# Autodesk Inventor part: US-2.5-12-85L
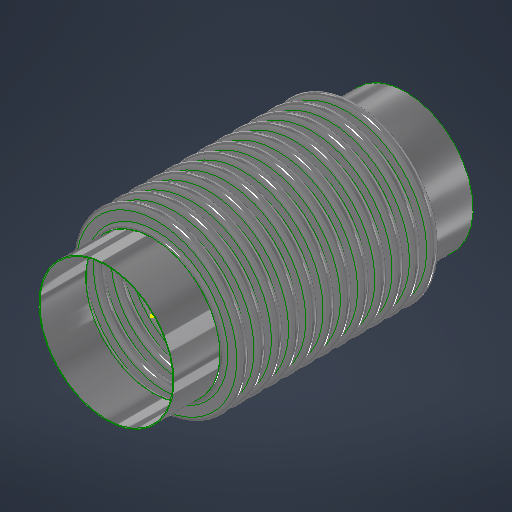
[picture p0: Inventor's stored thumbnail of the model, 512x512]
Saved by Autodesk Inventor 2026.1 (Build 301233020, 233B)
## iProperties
Category: 26 GA (0.018 THICK)
RuleStatus: InUse
Created: 2026-07
Part Number: US-2.5-12-85L
Project: =STOCK BELLOWS: <Stock Number><SFILL>
Material: ASTM A240-304
Description: =STOCK BELLOWS: <Stock Number>, <SID_> I.D., <SOD_> O.D., <SPLY_> PLY, <Category>, <SNET_CONS> CONS.<PITCH_><STANGENT_> TANGENT<SFILL>
Document SubType Name: Sheet Metal
Designer: LC
Stock Number: U.S-2.5-12-85L
Surface Area: 659.127 cm^2
Volume: 56.61 cm^3
Sheet Metal Rule: Default
Appearance: STAINLESS STEEL
NET_TUBE: 3.428
COUNTER: 1.500
PBAR: 1.214
PSET: 5.356
PLY: 2
CONS: 2
THK: 0.036
ID: 4.500
OD: 5.500
CONS_: 2
TANGENT: 0.500
PITCH: 0.375
BELLOWS_UPSET: 0.000
NET_CONS: 2
S_CONS: 0
Description_Units: 0
ID_M: 114.30 mm
OD_M: 139.70 mm
THK_M: 0.91 mm
ID_U: 4.500 in
OD_U: 5.500 in
THK_U: 0.036 in
TANGENT2: 0.500
d79: 1.000
d82: 1.000
d83: 26.000
d84: 24.000
d80: 2.571
d81: 10
SID: 2.375
SCONS_: 12
SPITCH: 0.250
SBELLOWS_UPSET: 0.000
SNET_CONS: 12
SS_CONS: 0
SCONS: 8
d174: 8
d177: 0.018
d178: 2.375
d179: 3.000
d180: 0.375
d181: 1.000
d182: 0.000
d190: 8
d191: 1
d192: 1
d193: 8
d194: 0
PART_NUMBER: U.S-2.5-12-85L
PRESSURE: 85
SIZE: 2.50
STANGENT_: 1.000
d214: 8
d217: 0.030
d218: 6.625
d219: 8.125
d220: 0.500
d221: 1.000
d222: 0.000
d230: 8
d231: 1
d232: 1
d233: 8
d234: 0
STANGENT: 4.000
SPLY_: 1
STHK_: 0.018
SID_: 2.900
SOD_: 3.700
SPITCH_: 0.375
STANGENT__: 1.000
SBELLOWS_UPSET_: 0.000
SDIFF_TAN: 1.000
TAN_TO_TAN: 0.750 in
d252: 2
d275: 2
d287: 0.050
d289: 0.500
d290: 0.000
d263: 2
d265: 1
d268: 2
d269: 0
d286: 2
d288: 1
d291: 2
d292: 0
SOD_NECK: 2 15/16
CFILL: .
SFILL: .
PITCH_: =, <SPITCH_> PITCH,
SREROLL: 0.750
MATTABLE: 20 GA (0.036 THICK)
MESH: ,
CSECT: 2
Author: LC
Keywords: 20 GA (0.036 THICK)
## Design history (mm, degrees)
sketch "Sketch2"
  geometry: L1 (0, -183.595)-(0, 600.956) reference; L2 (58.979, 0)-(57.15, 0); L3 (60.446, -1.467)-(66.554, -1.467); L4 (60.446, -3.296)-(66.554, -3.296); L5 (66.554, -8.058)-(60.446, -8.058); L6 (66.554, -6.229)-(60.446, -6.229); L7 (58.979, -9.525)-(57.15, -9.525); L8 (60.446, 0)-(60.446, -9.525); L9 (66.554, -4.762)-(69.85, -4.763); L10 (57.15, 0)-(57.15, -9.525); L11 (20.376, 102.841)-(20.376, 101.926); L12 (58.262, 488.877)-(58.262, 349.177); L13 (58.262, 479.352)-(58.262, 339.652); L14 (93.133, -58.817)-(93.133, -71.517); L15 (118.746, -66.401)-(118.746, -66.401); L16 (66.554, -6.229)-(66.554, -8.058); L17 (60.446, -6.229)-(60.446, -8.058); L18 (60.446, -7.144)-(66.554, -7.144); L19 (69.85, 0)-(69.85, -9.525); L20 (-66.554, -6.229)-(-66.554, -8.058); L21 (-66.554, -1.467)-(-60.446, -1.467); L22 (-66.554, -3.296)-(-60.446, -3.296); L23 (-60.446, -6.229)-(-66.554, -6.229); L24 (-66.554, -7.144)-(-60.446, -7.144); L25 (-60.446, -8.058)-(-66.554, -8.058); L26 (-60.446, -6.229)-(-60.446, -8.058); L27 (-57.15, -2.522)-(-57.15, -12.047); L28 (-60.446, -4.763)-(-57.15, -4.763); L29 (-66.554, 3.828)-(-66.554, -9.525); L30 (-68.021, 0)-(-69.85, 0); L31 (-69.85, 0)-(-69.85, -9.525); L32 (-68.021, -9.525)-(-69.85, -9.525); A1 r 1.467 centre (60.446, 0) between (58.979, 0) and (60.446, -1.467); A2 r 3.296 centre (60.446, 0) between (57.15, 0) and (60.446, -3.296); A3 r 3.296 centre (66.554, -4.762) between (66.554, -8.058) and (66.554, -1.467); A4 r 1.467 centre (66.554, -4.762) between (66.554, -6.229) and (66.554, -3.296); A5 r 1.467 centre (60.446, -9.525) between (60.446, -8.058) and (58.979, -9.525); A6 r 3.296 centre (60.446, -9.525) between (60.446, -6.229) and (57.15, -9.525); A7 r 2.381 centre (66.554, -4.762) between (66.554, -7.144) and (68.936, -4.762); A8 r 2.381 centre (60.446, -9.525) between (60.446, -7.144) and (58.064, -9.525); A9 r 1.467 centre (-66.554, -9.525) between (-66.554, -8.058) and (-68.021, -9.525); A10 r 1.467 centre (-60.446, -4.763) between (-60.446, -6.229) and (-60.446, -3.296); A11 r 2.381 centre (-60.446, -4.763) between (-60.446, -7.144) and (-58.064, -4.763); A12 r 3.296 centre (-60.446, -4.763) between (-60.446, -8.058) and (-60.446, -1.467); A13 r 2.381 centre (-66.554, -9.525) between (-66.554, -7.144) and (-68.936, -9.525); A14 r 3.296 centre (-66.554, -9.525) between (-66.554, -6.229) and (-69.85, -9.525); A15 r 1.467 centre (-66.554, 0) between (-68.021, 0) and (-66.554, -1.467); A16 r 3.296 centre (-66.554, 0) between (-69.85, 0) and (-66.554, -3.296); 10 further points
  constraints: 62 end point, 38 point on circle, 20 tangent, 16 centre point, 12 parallel, 9 midpoint, 7 vertical, 6 coincident, 6 concentric, 6 point on line, 4 equal radius, 4 perpendicular, 3 horizontal, 1 collinear, 1 horizontal alignment, 10 other
  dimensions: "THK" = 0.9144 distance of L11.start L11.end; "ID" = 114.3 distance of L11.end point (20.376, -12.374); "OD" = 139.7 distance of L12.start L12.end; "PITCH" = 9.525 distance of L12.start L13.start; "TANGENT" = 12.7 distance of L14.start L14.end; "BELLOWS_UPSET" = 0 distance of L15.start L15.end; "d43" = 114.3 diameter of L10 L1 (= ID); "d44" = 139.7 diameter of L9.end L1 (= OD); "d45" = 1.8288 distance between parallel lines of L5 L6 (computed from THK, PLY); "d46" = 3.29565 radius of A3 (computed from PITCH, THK, PLY); "UPSET_PITCH" = 9.525 distance of L2.end L7.end (derived); "SIDEWALL_ANGLE" = 0 deg angle of L3 L9 (derived); "CON_GAP" = 2.9337 distance of point (60.446, -6.229) point (60.446, -3.296) (derived); "TAN1" = 3.74046 dimension on A8 (derived); "TAN2" = 3.74046 dimension on A7 (derived); "LEG1" = 6.1087 distance of L18.start L18.end (derived); "d278" = 1.8288 distance between parallel lines of L25 L23 (derived); "d279" = 3.29565 radius of A12 (derived); "d280" = 9.525 distance of L30.end L31.end (derived); "d281" = 360 deg dimension on L21 L28 (derived); "d282" = 2.9337 distance of point (-66.554, -6.229) point (-66.554, -3.296) (derived); "d283" = 3.74046 dimension on A13 (derived); "d284" = 3.74046 dimension on A11 (derived); "d285" = 6.1087 distance of L24.start L24.end (derived); "d293" = 114.3 diameter of L27 L1 (derived); "d294" = 139.7 diameter of L31 L1 (derived)
  node "Sketch Rectangular Pattern1" dims "d31" = 25.4, "ID" = 114.3
  node "Sketch Rectangular Pattern2" dims "d39" = 25.4, "PITCH" = 9.525
revolve "CONS" stored, may be unused: angle "d48" = 90 deg
node "BELLOW MIDPLANE"
pattern_linear "Rectangular Pattern2" dims "d52" = 9.525 (= UPSET_PITCH)
sketch "Sketch5"
  geometry: C1 r 58.979 at (0, 0) reference; C2 r 57.15 at (0, 0) reference
extrude "TANGENT" new body sketch "Sketch5" distance "d53" = 12.7 (= TANGENT); taper "d54" = 0 deg
revolve "SAMETAN" stored, may be unused: angle "d65" = 90 deg
revolve "DIFFTAN" stored, may be unused: angle "d70" = 90 deg
sketch "Sketch9"
  geometry: L1 (58.391, 0)-(-58.391, 0) reference; L2 (0, -17.78)-(0, 17.78) reference; L3 (41.708, 0)-(-41.708, 0); L4 (41.708, -11.906)-(41.708, 11.906); L5 (29.008, -11.906)-(29.008, 11.906); L6 (15.418, 11.906)-(15.418, -11.906); L7 (-29.008, -11.906)-(-29.008, 11.906); L8 (-41.708, -11.906)-(-41.708, 11.906); L9 (40.914, -11.906)-(40.914, 11.906); L10 (41.708, -11.906)-(40.914, -11.906); L11 (41.708, 11.906)-(40.914, 11.906); L12 (15.815, 11.906)-(15.022, 11.906); L13 (15.022, 11.906)-(15.022, -11.906); L14 (15.022, -11.906)-(15.815, -11.906); L15 (15.815, -11.906)-(15.815, 11.906); L16 (-15.815, 11.906)-(-15.815, -11.906); L17 (-15.418, 11.906)-(-15.418, -11.906); L18 (-15.815, -11.906)-(-15.022, -11.906); L19 (-15.022, -11.906)-(-15.022, 11.906); L20 (-15.022, 11.906)-(-15.815, 11.906); L21 (-41.708, -11.906)-(-40.914, -11.906); L22 (-40.914, -11.906)-(-40.914, 11.906); L23 (-40.914, 11.906)-(-41.708, 11.906); L24 (-41.708, 11.906)-(-41.708, -11.906); L25 (41.708, -0.397)-(-41.708, -0.397); L26 (-41.708, -0.397)-(-41.708, 0.397); L27 (-41.708, 0.397)-(41.708, 0.397); L28 (41.708, 0.397)-(41.708, -0.397); L29 (-41.708, 11.906)-(41.708, 11.906); L30 (41.708, 11.906)-(41.708, 12.7); L31 (41.708, 12.7)-(-41.708, 12.7); L32 (-41.708, 12.7)-(-41.708, 11.906); L33 (41.708, -11.906)-(-41.708, -11.906); L34 (-41.708, -11.906)-(-41.708, -12.7); L35 (-41.708, -12.7)-(41.708, -12.7); L36 (41.708, -12.7)-(41.708, -11.906); 30 further points
  constraints: 68 end point, 13 midpoint, 13 parallel, 8 horizontal, 7 perpendicular, 6 equal length, 3 point on line, 2 vertical, 14 other
  dimensions: "d115" = 23.8125 distance of L4.start L4.end (derived); "d116" = 12.7 distance between parallel lines of L4 L5 (derived); "d117" = 13.58962 distance between parallel lines of L5 L6 (derived); "d125" = 44.42645 distance between parallel lines of L7 L6 (derived); "d127" = 12.7 distance between parallel lines of L8 L7 (derived); "d128" = 26.28962 distance between parallel lines of L6 L4 (derived); "d130" = 83.41607 distance between parallel lines of L8 L4 (derived); "RULER_THK" = 0.79375 distance between parallel lines of L4 L9; "d135" = 0.79375 distance of L13.end L14.end (derived); "d138" = 30.83684 distance of L13.end L16.end (derived); "d143" = 0.79375 distance of L22.end L8.end (derived); "d144" = 0.79375 distance between parallel lines of L27 L25 (derived)
extrude "RULER" join sketch "Sketch9" distance "d149" = 0.79375 (derived); taper "d150" = 0 deg
extrude "BARS" join sketch "Sketch9" distance "d151" = 0.79375 (derived); taper "d152" = 0 deg
pattern_linear "Rectangular Pattern4" dims "d155" = 30.83684 (derived)
sketch "Sketch13"
  geometry: L1 (93.149, -52.467)-(93.149, -77.867); L2 (37.287, 0)-(36.83, 0); L3 (37.287, -9.525)-(36.83, -9.525); L4 (44.38, -7.372)-(39.44, -7.372); L5 (44.38, -6.915)-(39.44, -6.915); L6 (44.38, -4.762)-(46.99, -4.762); L7 (39.44, -2.153)-(44.38, -2.153); L8 (39.44, 0)-(39.44, -9.525); L9 (36.83, 0)-(36.83, -9.525); L10 (58.254, -367.738)-(58.254, -461.718); L11 (58.254, -377.263)-(58.254, -471.243); L12 (58.254, -396.313)-(58.254, -490.293); L13 (58.254, -405.838)-(58.254, -499.818); L14 (58.254, -415.363)-(58.254, -509.343); L15 (58.254, -424.888)-(58.254, -518.868); L16 (58.254, -434.413)-(58.254, -528.393); L17 (58.254, -386.788)-(58.254, -480.768); L18 (20.376, 102.383)-(20.376, 101.926); L19 (39.44, -2.61)-(44.38, -2.61); L20 (0, -640.324)-(0, 226.168) reference; L21 (-23.752, 0)-(142.514, 0) reference; A1 r 2.153 centre (39.44, 0) between (37.287, 0) and (39.44, -2.153); A2 r 2.153 centre (39.44, -9.525) between (39.44, -7.372) and (37.287, -9.525); A3 r 2.61 centre (39.44, -9.525) between (39.44, -6.915) and (36.83, -9.525); A4 r 2.153 centre (44.38, -4.762) between (44.38, -6.915) and (44.38, -2.61); A5 r 2.61 centre (44.38, -4.762) between (44.38, -7.372) and (44.38, -2.153); A6 r 2.61 centre (39.44, 0) between (36.83, 0) and (39.44, -2.61); 6 further points; 1 other entity
  constraints: 38 end point, 15 point on circle, 9 tangent, 6 centre point, 6 parallel, 5 vertical alignment, 4 point on line, 4 vertical, 3 coincident, 3 concentric, 2 collinear, 2 equal radius, 1 horizontal, 1 perpendicular, 23 other
  dimensions: "SBELLOWS_UPSET_" = 0 distance of point (118.762, -66.401) point (118.762, -66.401); "STOTAL_THK_BELLOW__" = 0.4572 distance between parallel lines of L4 L5 (derived); "d224" = 2.60985 radius of A5 (derived); "d225" = 9.525 distance of L2.end L3.end (derived); "SSIDEWALL_ANGLE_" = 0 deg angle of L7 L6 (derived); "SSCON_GAP_" = 4.3053 distance of point (39.44, -6.915) point (39.44, -2.61) (derived); "d235" = 73.66 diameter of L9 L20 (derived); "d236" = 93.98 diameter of L6.end L20 (derived)
  node "Sketch Rectangular Pattern4" dims "d228" = 25.4
  node "Sketch Rectangular Pattern5" dims "d229" = 25.4
revolve "SBELLOW" stored, may be unused: angle "d197" = 90 deg
pattern_linear "Rectangular Pattern5" dims "d204" = 9.525 (derived)
revolve "STANGENT" stored, may be unused: angle "d240" = 90 deg
revolve "SSAMETAN" stored, may be unused: angle "d241" = 90 deg
revolve "SDIFFTAN" stored, may be unused: angle "d246" = 90 deg
revolve "INVCON" stored, may be unused: angle "d295" = 90 deg
pattern_linear "Rectangular Pattern6" dims "d298" = 9.525 (derived)
revolve "INVTANGENT" stored, may be unused: angle "d302" = 90 deg
revolve "INVSAMETAN" stored, may be unused: angle "d307" = 90 deg
revolve "INVDIFFTAN" stored, may be unused: angle "d312" = 90 deg
sketch "ID BELLOW MOUNT CALC"
  geometry: L1 (44.45, 0)-(38.1, 0); L2 (38.1, 0)-(38.1, 12.7); L3 (38.1, 12.7)-(44.45, 12.7); L4 (44.45, 12.7)-(44.45, 0); L5 (36.513, 12.7)-(34.684, 12.7); L6 (34.684, 12.7)-(34.684, 0); L7 (34.684, 0)-(36.513, 0); L8 (36.513, 0)-(36.513, 12.7); L9 (0, -2.54)-(0, 15.24) reference; L10 (-8.89, 0)-(53.34, 0) reference; 1 further point
  constraints: 16 end point, 5 parallel, 2 collinear, 2 horizontal, 2 perpendicular
  dimensions: "d314" = 12.7 distance of L5.end L6.end (derived); "d315" = 1.8288 distance of L5.start L5.end (derived); "IG" = 1.5875 distance between parallel lines of L2 L8; "PIPE_OD" = 88.9 diameter of L4 L9; "PIPE_WALL" = 6.35 distance of L2.end L3.end; "ID_MT_BELLOW" = 69.3674 diameter of L6 L9 (derived)
revolve "CFILL" stored, may be unused: angle "d320" = 90 deg
pattern_linear "Rectangular Pattern7" dims "d323" = 9.525 (derived)
revolve "SFILL" stored, may be unused: angle "d324" = 90 deg
pattern_linear "Rectangular Pattern8" dims "d327" = 9.525 (derived)
node "STOCK BELLOW MIDPLANE"
sketch "Sketch21"
  geometry: L1 (0, -100.013)-(0, 100.013) reference; L2 (-100.013, 0)-(100.013, 0) reference; L3 (-0.099, 71.437)-(0.099, 71.437); L4 (0.099, 71.437)-(0.099, 55.562); L5 (0.099, 55.562)-(-0.099, 55.562); L6 (-0.099, 55.562)-(-0.099, 71.437); C1 r 55.562 at (0, 0); C2 r 71.437 at (0, 0); 3 further points
  constraints: 8 end point, 2 centre point, 2 coincident, 2 parallel, 2 tangent, 1 horizontal, 1 perpendicular, 1 other
  dimensions: "d329" = 111.125 diameter of C1 (derived); "d330" = 142.875 diameter of C2 (derived); "d331" = 0.19844 distance of L3.start L3.end
extrude "CLAMSHELL" cut sketch "Sketch21" extent not by distance; stored distance "d332" = 0; taper "d333" = 0 deg
pattern_circular "Circular Pattern1" dims angle "d335" = 180 deg (derived)
node "BELLOW"
sketch "Sketch6"
  geometry: L1 (-19.05, 58.979)-(-6.35, 58.979); L2 (-6.35, 58.979)-(-6.35, 57.15); L3 (-6.35, 57.15)-(-19.05, 57.15); L4 (-19.05, 57.15)-(-19.05, 58.979); L5 (2.54, 0)-(-59.69, 0) reference; L6 (-38.1, -108.388)-(-38.1, 156.601) reference; 1 further point
  constraints: 8 end point, 2 parallel, 1 horizontal, 1 perpendicular
  dimensions: "d61" = 12.7 distance of L2.end L3.end (derived); "d62" = 1.8288 distance of L1.end L2.end (derived); "d63" = 114.3 diameter of L3 L5 (derived); "d64" = 19.05 distance between parallel lines of L4 L6 (derived)
sketch "Sketch12"
  geometry: 1 further point
sketch "Sketch14"
  geometry: L1 (-25.4, 37.287)-(0, 37.287); L2 (0, 37.287)-(0, 36.83); L3 (0, 36.83)-(-25.4, 36.83); L4 (-25.4, 36.83)-(-25.4, 37.287); L5 (5.08, 0)-(-30.48, 0) reference; L6 (0, -8.89)-(0, 53.34) reference; 1 further point
  constraints: 8 end point, 2 parallel, 1 collinear, 1 horizontal, 1 perpendicular
  dimensions: "d237" = 0.4572 distance of L3.end L1.start (derived); "d238" = 73.66 diameter of L3 L5 (derived); "d239" = 25.4 distance of L1.start L1.end (derived); "SOD_NECK" = 74.5744 diameter of L1 L5 (derived)
sketch "Sketch15"
  geometry: L1 (-8.89, 0)-(53.34, 0) reference; L2 (36.83, -114.3)-(37.287, -114.3); L3 (37.287, -114.3)-(37.287, -139.7); L4 (37.287, -139.7)-(36.83, -139.7); L5 (36.83, -139.7)-(36.83, -114.3); L6 (0, -170.18)-(0, 43.18) reference; 1 further point
  constraints: 8 end point, 2 parallel, 1 horizontal, 1 perpendicular
  dimensions: "d205" = 25.4 distance of L4.end L2.start (derived); "d206" = 0.4572 distance of L3.end L4.end (derived); "d207" = 73.66 diameter of L5 L6 (derived); "d208" = 114.3 distance between parallel lines of L1 L2 (derived)
node "TANGENT_"
node "SAME_TAN"
sketch "Sketch8"
  geometry: L1 (58.979, -19.05)-(57.15, -19.05); L2 (57.15, -19.05)-(57.15, -31.75); L3 (57.15, -31.75)-(58.979, -31.75); L4 (58.979, -31.75)-(58.979, -19.05); L5 (0, -40.64)-(0, 21.59) reference; L6 (-108.388, 0)-(156.601, 0) reference; 1 further point
  constraints: 8 end point, 2 parallel, 1 horizontal, 1 perpendicular
  dimensions: "d66" = 114.3 diameter of L2 L5 (derived); "TOTAL_THK_BELLOW" = 1.8288 distance of L2.end L3.end (derived); "d68" = 19.05 distance between parallel lines of L1 L6 (derived); "d69" = 12.7 distance of L1.end L2.end (derived)
node "DIFF_TAN"
node "Sketch Rectangular Pattern3" dims "d138" = 30.83684 (derived), "d141" = 25.4
node "SBELLOW_"
node "STANGENT_"
node "SSAME_TAN"
sketch "Sketch16"
  geometry: L1 (37.287, -114.3)-(36.83, -114.3); L2 (36.83, -114.3)-(36.83, -139.7); L3 (36.83, -139.7)-(37.287, -139.7); L4 (37.287, -139.7)-(37.287, -114.3); L5 (0, -170.18)-(0, 43.18) reference; L6 (-8.89, 0)-(53.34, 0) reference; 1 further point
  constraints: 8 end point, 2 parallel, 1 horizontal, 1 perpendicular
  dimensions: "SDIFF_TAN" = 25.4 distance of L3.end L1.start; "d243" = 0.4572 distance of L2.end L3.end (derived); "d244" = 114.3 distance between parallel lines of L1 L6 (derived); "d245" = 73.66 diameter of L2 L5 (derived)
node "SDIFF_TAN"
body "Solid15"
sketch "Sketch17"
  geometry: L1 (69.85, 12.7)-(68.021, 12.7); L2 (68.021, 12.7)-(68.021, 0); L3 (68.021, 0)-(69.85, 0); L4 (69.85, 0)-(69.85, 12.7); L5 (0, -2.54)-(0, 15.24) reference; L6 (-13.97, 0)-(83.82, 0) reference; 2 further points
  constraints: 8 end point, 2 parallel, 1 horizontal, 1 midpoint, 1 perpendicular, 1 point on line
  dimensions: "INVTANGENT" = 12.7 distance of L3.end L1.start (derived); "d300" = 1.8288 distance of L1.start L1.end (derived); "d301" = 139.7 diameter of L4 L5 (derived)
body "Solid16"
sketch "Sketch18"
  geometry: L1 (69.85, -19.05)-(68.021, -19.05); L2 (68.021, -19.05)-(68.021, -31.75); L3 (68.021, -31.75)-(69.85, -31.75); L4 (69.85, -31.75)-(69.85, -19.05); L5 (-13.97, 0)-(83.82, 0) reference; L6 (0, -40.64)-(0, 21.59) reference; 1 further point
  constraints: 8 end point, 2 parallel, 1 horizontal, 1 perpendicular
  dimensions: "d303" = 19.05 distance between parallel lines of L1 L5 (derived); "d304" = 12.7 distance of L3.end L1.start (derived); "d305" = 1.8288 distance of L2.end L3.end (derived); "d306" = 139.7 diameter of L4 L6 (derived)
body "Solid17"
sketch "Sketch19"
  geometry: L1 (69.85, -19.05)-(68.021, -19.05); L2 (68.021, -19.05)-(68.021, -31.75); L3 (68.021, -31.75)-(69.85, -31.75); L4 (69.85, -31.75)-(69.85, -19.05); L5 (0, -40.64)-(0, 21.59) reference; L6 (-13.97, 0)-(83.82, 0) reference; 1 further point
  constraints: 8 end point, 2 parallel, 1 horizontal, 1 perpendicular
  dimensions: "d308" = 12.7 distance of L1.end L2.end (derived); "d309" = 139.7 diameter of L4 L5 (derived); "d310" = 1.8288 distance of L2.end L3.end (derived); "d311" = 19.05 distance between parallel lines of L1 L6 (derived)
body "Solid18"
body "Solid19"
body "Solid20"
other parameters: "BMPL" = -57.15, "PSET" = 136.0424 (computed from OD, THK, PLY) [user parameter], "PBAR" = 30.83684 (= 0.570796 x PITCH + OD - ID) [user parameter; used in 1 equation term], "COUNTER" = 15 [user parameter], "NET_TUBE" = 87.07367 (computed from CONS_, PBAR, TANGENT) [user parameter], "S_CONS" = 0 [user parameter; used in 1 equation term], "ID_M" = 114.3 (= ID) [user parameter], "OD_M" = 139.7 (= OD) [user parameter], "THK_M" = 0.9144 (= THK) [user parameter], "ID_U" = 114.3 (= ID) [user parameter], "OD_U" = 139.7 (= OD) [user parameter], "THK_U" = 0.9144 (= THK) [user parameter], "D_UNITS" = 0 [user parameter], "TANGENT2" = 12.7 [user parameter], "TAN_TO_TAN" = 19.05 [user parameter], "OD_NECK" = 117.9576 [user parameter], "d79" = 25.4, "d80" = 65.29823 [user parameter], "d82" = 25.4, "d83" = 660.4, "d84" = 609.6, "sa_0" = 4, "FRAME_THK" = 0.79375 [user parameter], "CON_FLAT" = 13.58962 [user parameter], "SID" = 60.325 [user parameter], "SPITCH" = 6.35 [user parameter], "STANGENT_" = 25.4 [user parameter], "SBELLOWS_UPSET" = 0 [user parameter], "SS_CONS" = 0 [user parameter], "STAN_TO_TAN_" = 114.3 [user parameter], "d100" = 0.4572 [user parameter], "d191" = 25.4 [user parameter], "d194" = 0 [user parameter], "STANGENT" = 101.6 [user parameter], "d234" = 0 [user parameter], "SUPSET_PITCH_" = 9.525 [user parameter], "d269" = 0 [user parameter], "d287" = 1.27, "d289" = 12.7, "d290" = 0, "d292" = 0 [user parameter], "Thickness" = 3.048 (derived), "KFactor" = 4.4, "BendRadius" = 3.048 (derived), "BendReliefWidth" = 3.048 (derived), "BendReliefDepth" = 1.524 (derived), "CornerReliefSize" = 12.192 (derived), "SeamGap" = 0.00508, "MinimumRemnant" = 6.096 (derived), "TransitionRadius" = 3.048 (derived), "JacobiRadiusSize" = 3.048 (derived), "GapSize" = 3.048 (derived), "SREROLL" = 19.05 [user parameter], "CUR_STK_PITCH" = 9.525 [user parameter], "d328" = -57.15 (derived), "CSECTDEG" = 180 deg [user parameter]
